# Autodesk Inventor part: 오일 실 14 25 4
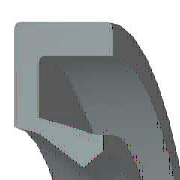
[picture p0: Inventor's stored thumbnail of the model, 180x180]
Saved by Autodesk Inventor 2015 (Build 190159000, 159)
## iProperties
Created: 2012-02
Part Number: 오일 실 14 25 4
Material: 고무
Description: 오일 실 - 스프링 장착, 비스프링, 고무 덮개 G
Document SubType Name: Modeling
Standard: JIS B 2402
Designer: mdu-01
Standards Organization: JIS
Language: ko-KR
Size Designation: 14 25 4 A
Categories: <MemberInstance><Categories><Category DisplayName="샤프트 부품" InternalName="7f7aeb1f-a693-4053-b835-cee3144e0d98" Mnemonic="SHFT"><Category DisplayName="실링" Intern
Density: 0.93 g/cm^3
Appearance: 고무 - 검은색 - 버전 1.1
IsCustomPart: 1
Author: mdu-01
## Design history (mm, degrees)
body "Solid1"
revolve "회전1" stored, may be unused: angle "d29" = 360 deg
chamfer "모따기1" distance "d30" = 0.2 (= 0.05 x b); stored, may be unused: second distance "d31" = 0.4 (= 0.1 x b), angle "d39" = 45 deg
chamfer "모따기2" distance "d32" = 0.4 (= 0.1 x b); stored, may be unused: second distance "d33" = 0.2 (= 0.05 x b), angle "d40" = 45 deg
fillet "모깎기1" dims "d34" = 0.2 (= 0.05 x b)
sketch "스케치2"
  geometry: L1 (7.914, -2.75)-(8.189, -4); L2 (7.547, -2.626)-(7.914, -2.75); L3 (7, -1.376)-(7.547, -2.626); L4 (8, -0.976)-(7, -1.376); L5 (8.956, -3)-(8, -0.976); L6 (10.056, -3)-(8.956, -3); L7 (11.278, -1)-(10.056, -3); L8 (11.278, 0)-(11.278, -1); L9 (12.5, 0)-(11.278, 0); L10 (12.5, -4)-(12.5, 0); L11 (8.189, -4)-(12.5, -4); L12 (0, -9.6)-(0, 1.6) reference; L13 (28, 0)-(14, 0) reference
  constraints: 22 end point, 3 horizontal, 2 vertical
  dimensions: "d2" = 4 distance of L10.start L9.start (= b); "d4" = 1 vertical distance of L5.start L1.end (= 0.25 x b); "d6" = 1.22222 distance of L9.start L8.start (= 0.111111 x dd - 0.111111 x Diam); "d8" = 1 distance of L8.start L7.start (= 0.25 x b); "d10" = 1.22222 horizontal distance of L7.start L6.start (= 0.111111 x dd - 0.111111 x Diam); "d12" = 0.97561 vertical distance of L9.start L4.start (= 0.243902 x b); "d14" = 1 horizontal distance of L4.start L3.start (= 0.0909091 x dd - 0.0909091 x Diam); "d16" = 0.4 vertical distance of L4.start L3.start (= 0.1 x b); "d18" = 1.1 distance of L6.start L5.start (= 0.1 x dd - 0.1 x Diam); "d20" = 1.25 vertical distance of L3.start L2.start (= 0.3125 x b); "d22" = 0.54726 horizontal distance of L3.start L2.start (= 0.0497512 x dd - 0.0497512 x Diam); "d24" = 0.275 horizontal distance of L1.start L1.end (= 0.025 x dd - 0.025 x Diam); "d26" = 1.25 vertical distance of L1.start L1.end (= 0.3125 x b); "d28" = 0.36667 horizontal distance of L2.start L1.start (= 0.0333333 x dd - 0.0333333 x Diam); "d35" = 0 distance between parallel lines of L13 L9; "d36" = 12.5 distance between parallel lines of L12 L10 (= 0.5 x dd); "d37" = 7 distance from line of L12 L3.start (= 0.5 x Diam)
other parameters: "dd" = 25 [user parameter; used in 8 equation terms], "Diam" = 14 [user parameter; used in 8 equation terms], "b" = 4 [user parameter; used in 12 equation terms], "d1" = 8 (derived), "d3" = 2 (derived), "d5" = 2.22222 (derived), "d7" = 2 (derived), "d9" = 2.22222 (derived), "d11" = 1.95122 (derived), "d13" = 1.81818 (derived), "d15" = 0.8 (derived), "d17" = 2 (derived), "d19" = 2.5 (derived), "d21" = 0.99502 (derived), "d23" = 0.5 (derived), "d25" = 2.5 (derived), "d27" = 0.66667 (derived), "d38" = 0
